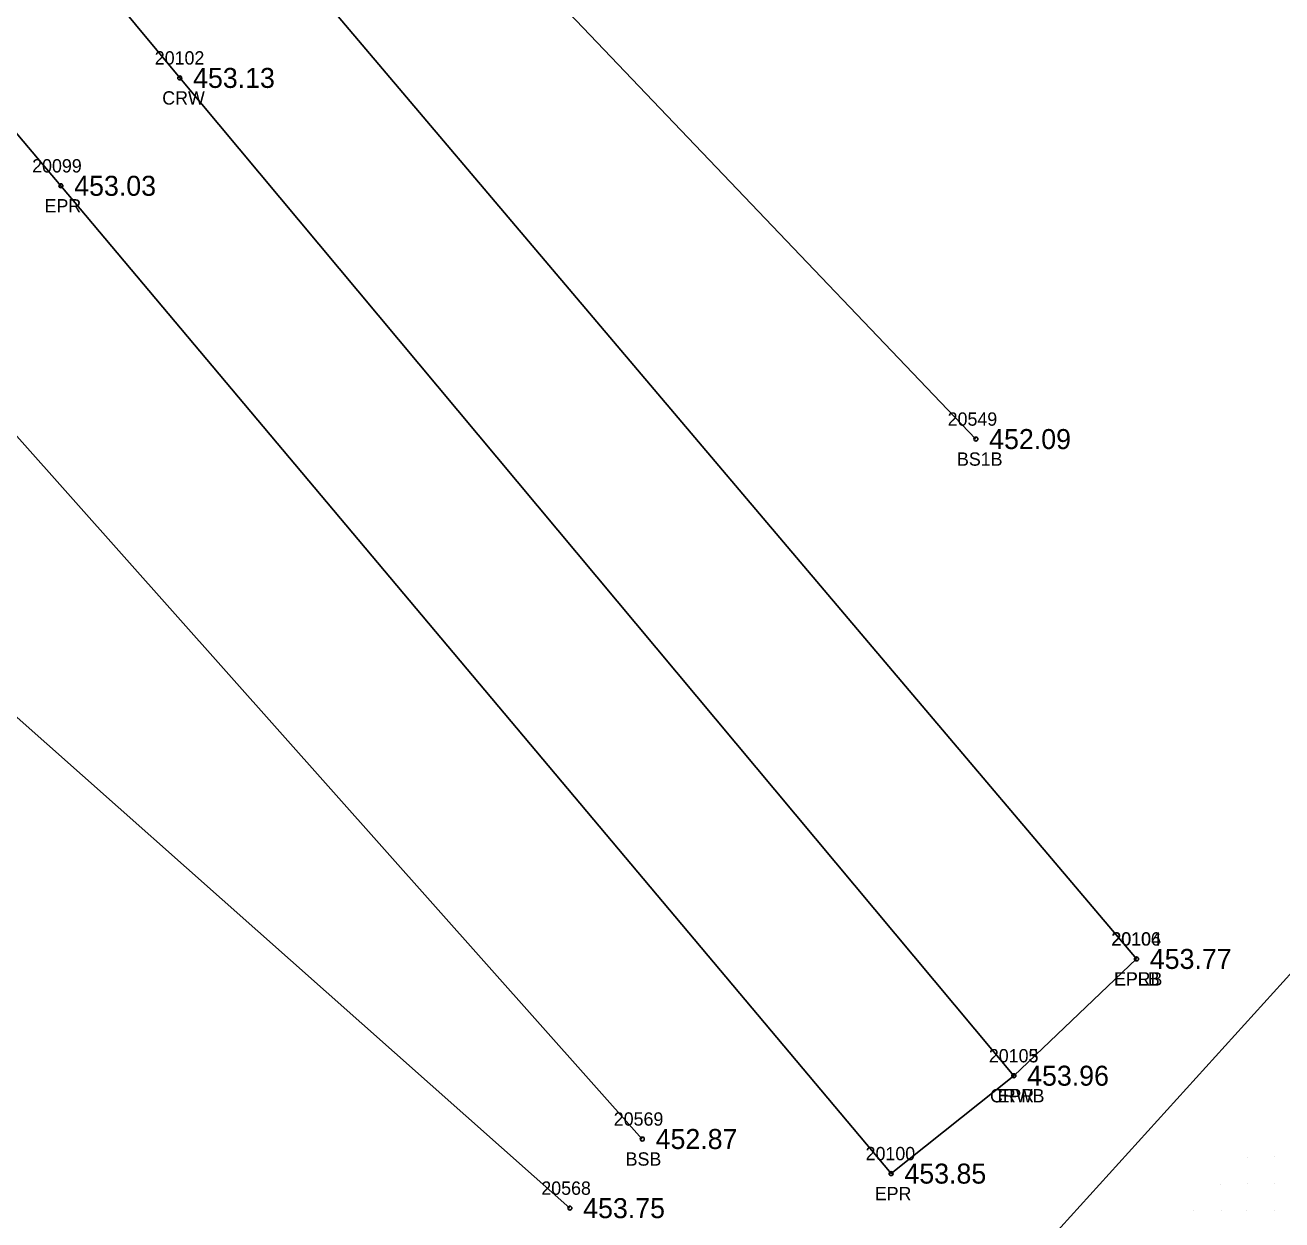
# Model space of a CAD drawing. Extents: x 1747760 to 1751131, y 649333 to 653784.
# Drawn here: x 1749005.6 to 1749099.9, y 651476.1 to 651565.7 of the extents above; entities that cross this region are included whole.
import ezdxf

# ---------------------------------------------------------------- set-up
doc = ezdxf.new("R2010")
doc.units = 0
for name, color, linetype in [('RD_DTM_BkLn1', 7, 'Continuous'), ('RD_DTM_BkLn2', 7, 'Continuous'), ('RD_DTM_BkLn_txCode', 7, 'Continuous'), ('RD_DTM_Spot', 7, 'Continuous'), ('RD_EX_Road', 7, 'Continuous'), ('RD_EX_Road_txCode', 7, 'Continuous'), ('RD_EX_TX_Misc_ELEV', 7, 'Continuous'), ('RD_EX_TX_Road_ELEV', 7, 'Continuous'), ('RD_HC_Survey_ELEV', 7, 'Continuous'), ('RD_HC_Survey_txCode', 7, 'Continuous'), ('RD_SMD_Locator', 7, 'Continuous')]:
    doc.layers.add(name, color=color, linetype=linetype)

msp = doc.modelspace()

# ---------------------------------------------------------------- linework, layer by layer
at = {"layer": 'RD_DTM_BkLn1'}
msp.add_lwpolyline([(1748421, 652569.861), (1748462.977, 652480.426), (1748505.93, 652389.746), (1748538.786, 652319.529), (1748579.367, 652232.853), (1748597.1, 652193.043), (1748620.952, 652141.839), (1748643.378, 652095.224), (1748665.52, 652051.657), (1748689.408, 652007.072), (1748713.81, 651963.4), (1748739.859, 651920.502), (1748766.994, 651879.007), (1748796.593, 651836.443), (1748826.339, 651795.119), (1748855.923, 651755.852), (1748886.768, 651717.258), (1748951.798, 651639.974), (1748989.549, 651595.12), (1749017.217, 651561.76), (1749079.789, 651486.925)], dxfattribs=at)
at = {"layer": 'RD_DTM_BkLn2'}
for points in [[(1748704.78, 652024.192), (1748734.936, 651973.427), (1748760.61, 651933.543), (1748794.062, 651893.444), (1748822.678, 651853.023), (1748847.434, 651814.197), (1748875.734, 651771.231), (1748911.24, 651735.351), (1748972.043, 651657.728), (1749035.867, 651577.685), (1749076.941, 651534.674)], [(1748807.775, 651779.201), (1748839.601, 651740.964), (1748868.924, 651701.824), (1748932.845, 651622.117), (1748997.315, 651543.487), (1749051.918, 651482.177)], [(1748813.419, 651752.224), (1748821.954, 651746.878), (1748830.052, 651733.372), (1748861.03, 651695.085), (1748918.761, 651610.1), (1748983.822, 651532.582), (1749046.483, 651476.991)], [(1749072.449, 651463.568), (1749102.17, 651496.369), (1749126.542, 651516.467), (1749148.35, 651529.918), (1749165.728, 651545.441)]]:
    msp.add_lwpolyline(points, dxfattribs=at)
at = {"layer": 'RD_DTM_Spot'}
for p, q in [((1749097.301, 651480.762), (1749097.301, 651480.762)), ((1749099.331, 651480.842), (1749099.331, 651480.842)), ((1749095.301, 651478.765), (1749095.301, 651478.765)), ((1749097.336, 651478.842), (1749097.336, 651478.842)), ((1749099.307, 651478.825), (1749099.307, 651478.825)), ((1749093.277, 651476.802), (1749093.277, 651476.802)), ((1749095.336, 651476.785), (1749095.336, 651476.785)), ((1749097.267, 651476.848), (1749097.267, 651476.848)), ((1749099.322, 651476.816), (1749099.322, 651476.816))]:
    msp.add_line(p, q, dxfattribs=at)
at = {"layer": 'RD_EX_Road'}
for points in [[(1748430.719, 652573.591), (1748472.299, 652485.071), (1748515.542, 652394.239), (1748548.404, 652323.995), (1748589.226, 652237.286), (1748607.117, 652198.86), (1748609.094, 652199.499), (1748633.389, 652147.733), (1748655.855, 652100.413), (1748677.164, 652057.635), (1748701.061, 652012.63), (1748725.116, 651970.468), (1748751.226, 651927.263), (1748777.837, 651886.082), (1748807.14, 651843.169), (1748836.628, 651802.605), (1748866.265, 651763.366), (1748897.62, 651724.521), (1748961.523, 651647.756), (1748997.975, 651603.488), (1749026.315, 651569.663), (1749088.991, 651495.683)], [(1748703.772, 651957.469), (1748729.932, 651914.237), (1748757.127, 651872.561), (1748787.318, 651828.584), (1748802.292, 651807.162), (1748814.232, 651790.243), (1748816.478, 651787.94), (1748845.697, 651749.017), (1748877.33, 651709.652), (1748941.982, 651631.918), (1748980.413, 651586.709), (1749008.301, 651553.669), (1749070.583, 651479.582), (1749079.789, 651486.925), (1749088.991, 651495.683)]]:
    msp.add_lwpolyline(points, dxfattribs=at)
at = {"layer": 'RD_SMD_Locator'}
for centre in [(1749017.217, 651561.76), (1749008.301, 651553.669), (1749076.941, 651534.674), (1749088.991, 651495.683), (1749088.991, 651495.683), (1749079.789, 651486.925), (1749079.789, 651486.925), (1749051.918, 651482.177), (1749070.583, 651479.582), (1749046.483, 651476.991)]:
    msp.add_circle(centre, 0.15, dxfattribs=at)

# ---------------------------------------------------------------- texts
at = {"layer": 'RD_DTM_BkLn_txCode'}
for s, p in [('20549', (1749074.823, 651535.674)), ('BS1B', (1749075.524, 651532.674)), ('20569', (1749049.776, 651483.177)), ('BSB', (1749050.666, 651480.177)), ('20568', (1749044.341, 651477.991))]:
    msp.add_text(s, height=1, dxfattribs=at).set_placement(p)
at = {"layer": 'RD_EX_Road_txCode'}
for s, p in [('20099', (1749006.144, 651554.669)), ('EPR', (1749007.073, 651551.669)), ('20106', (1749087.093, 651496.683)), ('20104', (1749087.117, 651496.683)), ('EPRB', (1749087.29, 651493.683)), ('EPLB', (1749087.314, 651493.683)), ('20105', (1749077.915, 651487.925)), ('EPR', (1749078.561, 651484.925)), ('20100', (1749068.669, 651480.582)), ('EPR', (1749069.354, 651477.582))]:
    msp.add_text(s, height=1, dxfattribs=at).set_placement(p)
at = {"layer": 'RD_EX_TX_Misc_ELEV'}
for s, p in [('452.09', (1749077.941, 651533.924)), ('452.87', (1749052.918, 651481.427)), ('453.75', (1749047.483, 651476.241))]:
    msp.add_text(s, height=1.5, dxfattribs=at).set_placement(p)
at = {"layer": 'RD_EX_TX_Road_ELEV'}
for s, p in [('453.03', (1749009.301, 651552.919)), ('453.77', (1749089.991, 651494.933)), ('453.77', (1749089.991, 651494.933)), ('453.96', (1749080.789, 651486.175)), ('453.85', (1749071.583, 651478.832))]:
    msp.add_text(s, height=1.5, dxfattribs=at).set_placement(p)
at = {"layer": 'RD_HC_Survey_ELEV'}
for s, p in [('453.13', (1749018.217, 651561.01)), ('453.96', (1749080.789, 651486.175))]:
    msp.add_text(s, height=1.5, dxfattribs=at).set_placement(p)
at = {"layer": 'RD_HC_Survey_txCode'}
for s, p in [('20102', (1749015.343, 651562.76)), ('CRW', (1749015.902, 651559.76)), ('20103', (1749077.915, 651487.925)), ('CRWB', (1749078.002, 651484.925))]:
    msp.add_text(s, height=1, dxfattribs=at).set_placement(p)

doc.saveas('drawing.dxf')
